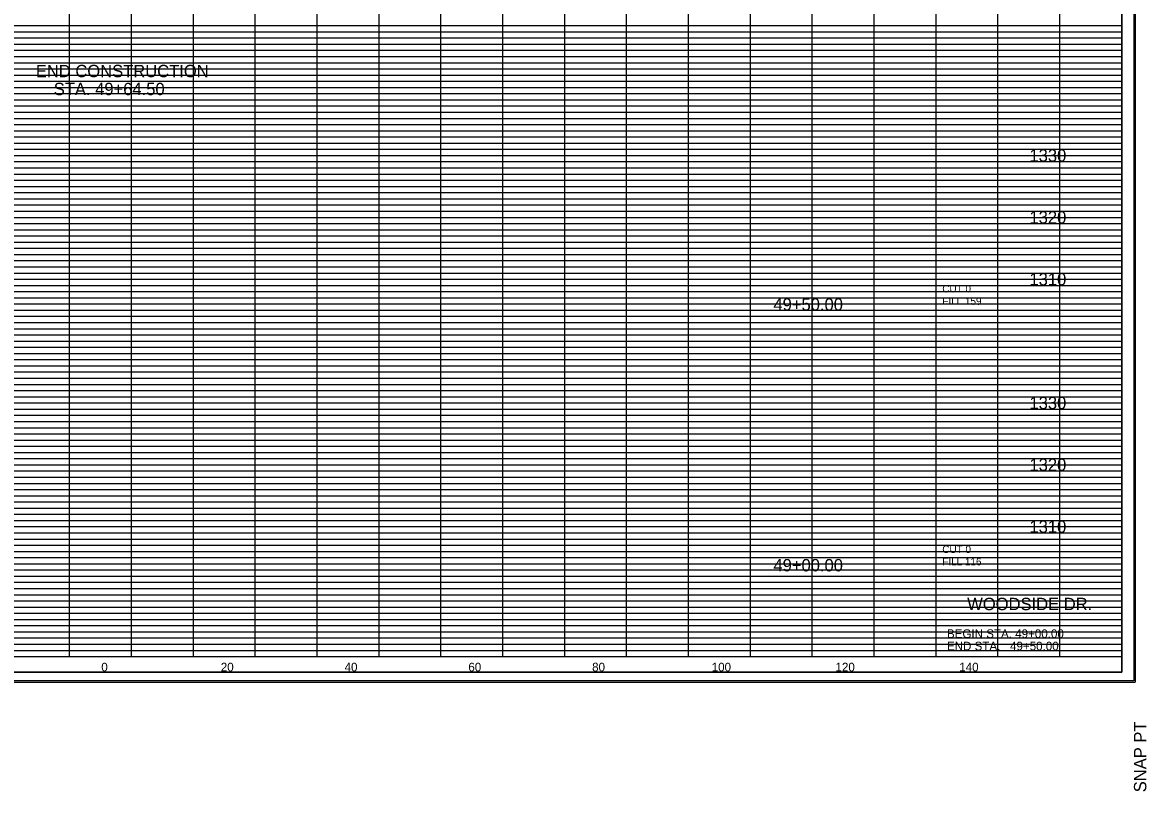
# Model space of a CAD drawing. Extents: x 980 to 1324, y 978 to 1497.
# Drawn here: x 1142.4 to 1324, y 1248.2 to 1372.5 of the extents above; entities that cross this region are included whole.
import ezdxf

# ---------------------------------------------------------------- set-up
doc = ezdxf.new("R2010")
doc.units = 0
for name, color, linetype in [('DESIGN - SHEET - Corner Text', 7, 'Continuous'), ('DESIGN - SHEET - Light Grid', 7, 'Continuous'), ('DESIGN - SHEET - Linework', 7, 'Continuous'), ('DESIGN - SHEET - Plot Shape', 7, 'Continuous'), ('DESIGN - TYPICAL - Finished Grade and Subgrade', 7, 'Continuous'), ('DESIGN - TYPICAL - Text', 7, 'Continuous')]:
    doc.layers.add(name, color=color, linetype=linetype)

# ---------------------------------------------------------------- blocks, each defined once
blk = doc.blocks.new('XSTSHT')
at = {"layer": 'DESIGN - SHEET - Light Grid'}
for p, q in [((8, 10.2), (16, 10.2)), ((16, 10.2), (24, 10.2)), ((24, 10.2), (32, 10.2)), ((8, 10.1), (16, 10.1)), ((16, 10.1), (24, 10.1)), ((24, 10.1), (32, 10.1)), ((8, 9.9), (16, 9.9)), ((16, 9.9), (24, 9.9)), ((24, 9.9), (32, 9.9)), ((8, 9.8), (16, 9.8)), ((8, 9.7), (16, 9.7)), ((16, 9.8), (24, 9.8)), ((16, 9.7), (24, 9.7)), ((24, 9.8), (32, 9.8)), ((24, 9.7), (32, 9.7)), ((8, 9.6), (16, 9.6)), ((8, 9.5), (16, 9.5)), ((16, 9.6), (24, 9.6)), ((16, 9.5), (24, 9.5)), ((24, 9.6), (32, 9.6)), ((24, 9.5), (32, 9.5)), ((8, 9.4), (16, 9.4)), ((8, 9.3), (16, 9.3)), ((16, 9.4), (24, 9.4)), ((16, 9.3), (24, 9.3)), ((24, 9.4), (32, 9.4)), ((24, 9.3), (32, 9.3)), ((8, 9.2), (16, 9.2)), ((8, 9.1), (16, 9.1)), ((16, 9.2), (24, 9.2)), ((16, 9.1), (24, 9.1)), ((24, 9.2), (32, 9.2)), ((24, 9.1), (32, 9.1)), ((8, 8.9), (16, 8.9)), ((16, 8.9), (24, 8.9)), ((24, 8.9), (32, 8.9)), ((8, 8.8), (16, 8.8)), ((16, 8.8), (24, 8.8)), ((24, 8.8), (32, 8.8)), ((8, 8.7), (16, 8.7)), ((8, 8.6), (16, 8.6)), ((16, 8.7), (24, 8.7)), ((16, 8.6), (24, 8.6)), ((24, 8.7), (32, 8.7)), ((24, 8.6), (32, 8.6)), ((8, 8.5), (16, 8.5)), ((8, 8.4), (16, 8.4)), ((16, 8.5), (24, 8.5)), ((16, 8.4), (24, 8.4)), ((24, 8.5), (32, 8.5)), ((24, 8.4), (32, 8.4)), ((8, 8.3), (16, 8.3)), ((8, 8.2), (16, 8.2)), ((16, 8.3), (24, 8.3)), ((16, 8.2), (24, 8.2)), ((24, 8.3), (32, 8.3)), ((24, 8.2), (32, 8.2)), ((8, 8.1), (16, 8.1)), ((16, 8.1), (24, 8.1)), ((24, 8.1), (32, 8.1)), ((8, 7.9), (16, 7.9)), ((16, 7.9), (24, 7.9)), ((24, 7.9), (32, 7.9)), ((8, 7.8), (16, 7.8)), ((8, 7.7), (16, 7.7)), ((16, 7.8), (24, 7.8)), ((16, 7.7), (24, 7.7)), ((24, 7.8), (32, 7.8)), ((24, 7.7), (32, 7.7)), ((8, 7.6), (16, 7.6)), ((8, 7.5), (16, 7.5)), ((16, 7.6), (24, 7.6)), ((16, 7.5), (24, 7.5)), ((24, 7.6), (32, 7.6)), ((24, 7.5), (32, 7.5)), ((8, 7.4), (16, 7.4)), ((8, 7.3), (16, 7.3)), ((16, 7.4), (24, 7.4)), ((16, 7.3), (24, 7.3)), ((24, 7.4), (32, 7.4)), ((24, 7.3), (32, 7.3)), ((8, 7.2), (16, 7.2)), ((8, 7.1), (16, 7.1)), ((16, 7.2), (24, 7.2)), ((16, 7.1), (24, 7.1)), ((24, 7.2), (32, 7.2)), ((24, 7.1), (32, 7.1)), ((8, 6.9), (16, 6.9)), ((8, 6.8), (16, 6.8)), ((16, 6.9), (24, 6.9)), ((16, 6.8), (24, 6.8)), ((24, 6.9), (32, 6.9)), ((24, 6.8), (32, 6.8)), ((8, 6.7), (16, 6.7)), ((8, 6.6), (16, 6.6)), ((16, 6.7), (24, 6.7)), ((16, 6.6), (24, 6.6)), ((24, 6.7), (32, 6.7)), ((24, 6.6), (32, 6.6)), ((8, 6.5), (16, 6.5)), ((8, 6.4), (16, 6.4)), ((16, 6.5), (24, 6.5)), ((16, 6.4), (24, 6.4)), ((24, 6.5), (32, 6.5)), ((24, 6.4), (32, 6.4)), ((8, 6.3), (16, 6.3)), ((8, 6.2), (16, 6.2)), ((16, 6.3), (24, 6.3)), ((16, 6.2), (24, 6.2)), ((24, 6.3), (32, 6.3)), ((24, 6.2), (32, 6.2)), ((8, 6.1), (16, 6.1)), ((16, 6.1), (24, 6.1)), ((24, 6.1), (32, 6.1)), ((8, 5.9), (16, 5.9)), ((16, 5.9), (24, 5.9)), ((24, 5.9), (32, 5.9)), ((8, 5.8), (16, 5.8)), ((8, 5.7), (16, 5.7)), ((16, 5.8), (24, 5.8)), ((16, 5.7), (24, 5.7)), ((24, 5.8), (32, 5.8)), ((24, 5.7), (32, 5.7)), ((8, 5.6), (16, 5.6)), ((8, 5.5), (16, 5.5)), ((16, 5.6), (24, 5.6)), ((16, 5.5), (24, 5.5)), ((24, 5.6), (32, 5.6)), ((24, 5.5), (32, 5.5)), ((8, 5.4), (16, 5.4)), ((8, 5.3), (16, 5.3)), ((16, 5.4), (24, 5.4)), ((16, 5.3), (24, 5.3)), ((24, 5.4), (32, 5.4)), ((24, 5.3), (32, 5.3)), ((8, 5.2), (16, 5.2)), ((8, 5.1), (16, 5.1)), ((16, 5.2), (24, 5.2)), ((16, 5.1), (24, 5.1)), ((24, 5.2), (32, 5.2)), ((24, 5.1), (32, 5.1)), ((8, 4.9), (16, 4.9)), ((8, 4.8), (16, 4.8)), ((16, 4.9), (24, 4.9)), ((16, 4.8), (24, 4.8)), ((24, 4.9), (32, 4.9)), ((24, 4.8), (32, 4.8)), ((8, 4.7), (16, 4.7)), ((8, 4.6), (16, 4.6)), ((16, 4.7), (24, 4.7)), ((16, 4.6), (24, 4.6)), ((24, 4.7), (32, 4.7)), ((24, 4.6), (32, 4.6)), ((8, 4.5), (16, 4.5)), ((8, 4.4), (16, 4.4)), ((16, 4.5), (24, 4.5)), ((16, 4.4), (24, 4.4)), ((24, 4.5), (32, 4.5)), ((24, 4.4), (32, 4.4)), ((8, 4.3), (16, 4.3)), ((8, 4.2), (16, 4.2)), ((16, 4.3), (24, 4.3)), ((16, 4.2), (24, 4.2)), ((24, 4.3), (32, 4.3)), ((24, 4.2), (32, 4.2)), ((8, 4.1), (16, 4.1)), ((16, 4.1), (24, 4.1)), ((24, 4.1), (32, 4.1)), ((8, 3.9), (16, 3.9)), ((16, 3.9), (24, 3.9)), ((24, 3.9), (32, 3.9)), ((8, 3.8), (16, 3.8)), ((8, 3.7), (16, 3.7)), ((16, 3.8), (24, 3.8)), ((16, 3.7), (24, 3.7)), ((24, 3.8), (32, 3.8)), ((24, 3.7), (32, 3.7)), ((8, 3.6), (16, 3.6)), ((8, 3.5), (16, 3.5)), ((16, 3.6), (24, 3.6)), ((16, 3.5), (24, 3.5)), ((24, 3.6), (32, 3.6)), ((24, 3.5), (32, 3.5)), ((8, 3.4), (16, 3.4)), ((8, 3.3), (16, 3.3)), ((16, 3.4), (24, 3.4)), ((16, 3.3), (24, 3.3)), ((24, 3.4), (32, 3.4)), ((24, 3.3), (32, 3.3)), ((8, 3.2), (16, 3.2)), ((8, 3.1), (16, 3.1)), ((16, 3.2), (24, 3.2)), ((16, 3.1), (24, 3.1)), ((24, 3.2), (32, 3.2)), ((24, 3.1), (32, 3.1)), ((8, 2.9), (16, 2.9)), ((8, 2.8), (16, 2.8)), ((16, 2.9), (24, 2.9)), ((16, 2.8), (24, 2.8)), ((24, 2.9), (32, 2.9)), ((24, 2.8), (32, 2.8)), ((8, 2.7), (16, 2.7)), ((8, 2.6), (16, 2.6)), ((16, 2.7), (24, 2.7)), ((16, 2.6), (24, 2.6)), ((24, 2.7), (32, 2.7)), ((24, 2.6), (32, 2.6)), ((8, 2.5), (16, 2.5)), ((8, 2.4), (16, 2.4)), ((16, 2.5), (24, 2.5)), ((16, 2.4), (24, 2.4)), ((24, 2.5), (32, 2.5)), ((24, 2.4), (32, 2.4)), ((8, 2.3), (16, 2.3)), ((8, 2.2), (16, 2.2)), ((16, 2.3), (24, 2.3)), ((16, 2.2), (24, 2.2)), ((24, 2.3), (32, 2.3)), ((24, 2.2), (32, 2.2)), ((8, 2.1), (16, 2.1)), ((16, 2.1), (24, 2.1)), ((24, 2.1), (32, 2.1)), ((8, 1.9), (16, 1.9)), ((16, 1.9), (24, 1.9)), ((24, 1.9), (32, 1.9)), ((8, 1.8), (16, 1.8)), ((8, 1.7), (16, 1.7)), ((16, 1.8), (24, 1.8)), ((16, 1.7), (24, 1.7)), ((24, 1.8), (32, 1.8)), ((24, 1.7), (32, 1.7)), ((8, 1.6), (16, 1.6)), ((8, 1.5), (16, 1.5)), ((16, 1.6), (24, 1.6)), ((16, 1.5), (24, 1.5)), ((24, 1.6), (32, 1.6)), ((24, 1.5), (32, 1.5)), ((8, 1.4), (16, 1.4)), ((8, 1.3), (16, 1.3)), ((16, 1.4), (24, 1.4)), ((16, 1.3), (24, 1.3)), ((24, 1.4), (32, 1.4)), ((24, 1.3), (32, 1.3)), ((8, 1.2), (16, 1.2)), ((8, 1.1), (16, 1.1)), ((16, 1.2), (24, 1.2)), ((16, 1.1), (24, 1.1)), ((24, 1.2), (32, 1.2)), ((24, 1.1), (32, 1.1)), ((8, 0.9), (16, 0.9)), ((8, 0.8), (16, 0.8)), ((16, 0.9), (24, 0.9)), ((16, 0.8), (24, 0.8)), ((24, 0.9), (32, 0.9)), ((24, 0.8), (32, 0.8)), ((8, 0.7), (16, 0.7)), ((8, 0.6), (16, 0.6)), ((16, 0.7), (24, 0.7)), ((16, 0.6), (24, 0.6)), ((24, 0.7), (32, 0.7)), ((24, 0.6), (32, 0.6)), ((8, 0.5), (16, 0.5)), ((8, 0.4), (16, 0.4)), ((16, 0.5), (24, 0.5)), ((16, 0.4), (24, 0.4)), ((24, 0.5), (32, 0.5)), ((24, 0.4), (32, 0.4)), ((8, 0.3), (16, 0.3)), ((8, 0.2), (16, 0.2)), ((16, 0.3), (24, 0.3)), ((16, 0.2), (24, 0.2)), ((24, 0.3), (32, 0.3)), ((24, 0.2), (32, 0.2)), ((8, 0.1), (16, 0.1)), ((16, 0.1), (24, 0.1)), ((24, 0.1), (32, 0.1))]:
    blk.add_line(p, q, dxfattribs=at)
at = {"layer": 'DESIGN - SHEET - Linework'}
for p, q in [((32.217, 21.414), (32.217, -0.414)), ((15, 0), (15, 21)), ((16, 0), (16, 21)), ((17, 0), (17, 21)), ((18, 0), (18, 21)), ((19, 0), (19, 21)), ((20, 0), (20, 21)), ((21, 0), (21, 21)), ((22, 0), (22, 21)), ((23, 0), (23, 21)), ((24, 0), (24, 21)), ((25, 0), (25, 21)), ((26, 0), (26, 21)), ((27, 0), (27, 21)), ((28, 0), (28, 20)), ((29, 0), (29, 20)), ((30, 0), (30, 20)), ((31, 0), (31, 20)), ((0, 10), (32, 10)), ((0, 9), (32, 9)), ((0, 8), (32, 8)), ((0, 7), (32, 7)), ((0, 6), (32, 6)), ((0, 5), (32, 5)), ((0, 4), (32, 4)), ((0, 3), (32, 3)), ((0, 2), (32, 2)), ((0, 1), (32, 1)), ((-1.823, -0.414), (32.217, -0.414))]:
    blk.add_line(p, q, dxfattribs=at)
blk.add_lwpolyline([(0, 21), (0, 0), (32, 0), (32, 21), (0, 21)], dxfattribs=at)
at = {"layer": 'DESIGN - SHEET - Plot Shape'}
for points in [[(-1.803, 21.394), (32.197, 21.394), (32.197, -0.394), (-1.803, -0.394)], [(-0.85, 21), (32, 21), (32, -0.25), (-0.85, -0.25)]]:
    blk.add_lwpolyline(points, close=True, dxfattribs=at)
at = {"layer": 'DESIGN - SHEET - Corner Text'}
blk.add_text('SNAP PT  ', height=0.2, rotation=90, dxfattribs=at).set_placement((32.397, -2.194))

msp = doc.modelspace()

# ---------------------------------------------------------------- linework, layer by layer
at = {"layer": 'DESIGN - SHEET - Plot Shape'}
msp.add_lwpolyline([(991.5, 1267.5), (1320, 1267.5), (1320, 1480), (991.5, 1480)], close=True, dxfattribs=at)

# ---------------------------------------------------------------- block references
at = {"layer": 'DESIGN - TYPICAL - Finished Grade and Subgrade', "xscale": 10, "yscale": 10}
msp.add_blockref('XSTSHT', (1000, 1270), dxfattribs=at)

# ---------------------------------------------------------------- texts
at = {"layer": 'DESIGN - SHEET - Corner Text'}
for s, height, p in [('WOODSIDE DR.', 2, (1295.02, 1277.5)), ('BEGIN STA. 49+00.00', 1.4, (1291.75, 1273)), ('END STA.   49+50.00', 1.4, (1291.75, 1271))]:
    msp.add_text(s, height=height, dxfattribs=at).set_placement(p)
at = {"layer": 'DESIGN - TYPICAL - Text'}
for s, height, p in [('END CONSTRUCTION', 2, (1144.53, 1363.65)), ('STA. 49+64.50', 2, (1147.43, 1360.75)), ('     1330     ', 2, (1301.37, 1350)), ('     1320     ', 2, (1301.37, 1340)), ('     1310     ', 2, (1301.37, 1330)), ('CUT 0', 1.2, (1291, 1328.86)), ('     49+50.00     ', 2, (1260, 1325.92)), ('FILL 159', 1.2, (1291, 1326.86)), ('     1330     ', 2, (1301.37, 1310)), ('     1320     ', 2, (1301.37, 1300)), ('     1310     ', 2, (1301.37, 1290)), ('CUT 0', 1.2, (1291, 1286.74)), ('FILL 116', 1.2, (1291, 1284.74)), ('     49+00.00     ', 2, (1260, 1283.77)), ('     0     ', 1.4, (1152.51, 1267.6)), ('     0     ', 1.4, (1152.51, 1267.6)), ('     20     ', 1.4, (1171.82, 1267.6)), ('     40     ', 1.4, (1191.82, 1267.6)), ('     60     ', 1.4, (1211.82, 1267.6)), ('     80     ', 1.4, (1231.82, 1267.6)), ('     100     ', 1.4, (1251.14, 1267.6)), ('     120     ', 1.4, (1271.14, 1267.6)), ('     140     ', 1.4, (1291.14, 1267.6))]:
    msp.add_text(s, height=height, dxfattribs=at).set_placement(p)

doc.saveas('drawing.dxf')
